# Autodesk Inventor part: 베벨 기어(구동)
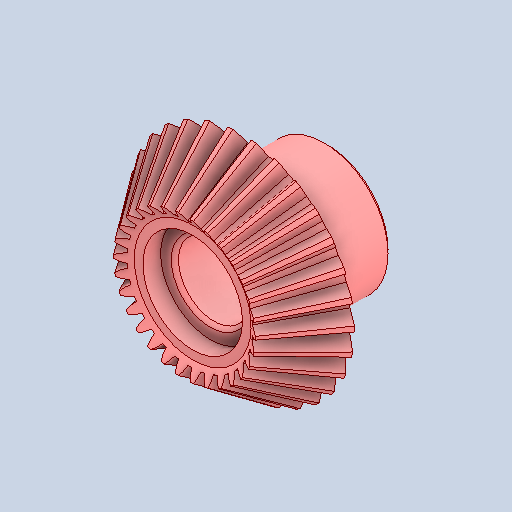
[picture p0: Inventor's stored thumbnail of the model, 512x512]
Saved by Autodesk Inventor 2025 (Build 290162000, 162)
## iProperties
Created: 2026-01
Part Number: 베벨 기어(구동)
Material: 강철, 합금
Document SubType Name: Modeling
Designer: KDI
Density: 7.73 g/cm^3
Appearance: 기본값
Author: jhkim
Sending System: Autodesk Inventor 2026
Preprocessor: ST-DEVELOPER v20.1
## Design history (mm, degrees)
feature "Solid1"
node "솔리드1"
